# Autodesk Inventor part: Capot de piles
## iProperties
Author: Flavien MARTY
Shininess: 20.0
PropertySet Name: _Private Model Information
Created: 2001-10
Part Number: Capot de piles
Material: Par défaut
Document SubType Name: Modélisation
Designer: Flavien MARTY
Control State: 0
Master: False
Checked Out: False
PropertySet Name: Design Tracking Control
Density: 0.0
Volumn: 0.0
Area: 0.0
PropertySet Name: Model Information
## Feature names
1. Base1
